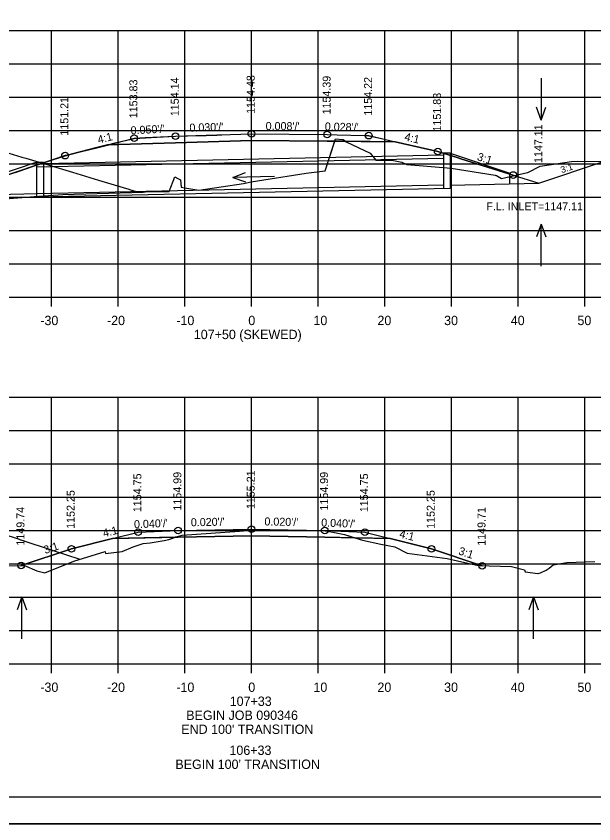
# Model space of a CAD drawing. Extents: x 1368971 to 1374497, y 378717 to 381839.
# Drawn here: x 1369607.6 to 1369694.3, y 378861.8 to 378982.9 of the extents above; entities that cross this region are included whole.
import ezdxf

# ---------------------------------------------------------------- set-up
doc = ezdxf.new("R2010")
doc.units = 0
for name, color, linetype in [('R_Alt Surface', 7, 'Continuous'), ('R_Axis', 7, 'Continuous'), ('R_Axis Annot', 7, 'Continuous'), ('R_Border', 7, 'Continuous'), ('R_Contours', 7, 'Continuous'), ('R_Exist Surface', 7, 'Continuous'), ('R_Fin Surface', 7, 'Continuous'), ('R_Grid', 7, 'Continuous'), ('R_No Plot', 7, 'Continuous'), ('R_Water', 7, 'Continuous'), ('R_Water Annot', 7, 'Continuous'), ('R_Xsect Elev', 7, 'Continuous'), ('R_Xsect Slope', 7, 'Continuous')]:
    doc.layers.add(name, color=color, linetype=linetype)

msp = doc.modelspace()

# ---------------------------------------------------------------- linework, layer by layer
at = {"layer": 'R_Alt Surface'}
for points in [[(1369621.37, 378963.63), (1369631.54, 378963.94), (1369642.93, 378964.29), (1369654.32, 378964.2), (1369664.49, 378964.11)], [(1369622.1, 378904.6), (1369631.93, 378904.8), (1369642.93, 378905.02), (1369653.93, 378904.8), (1369663.76, 378904.6)]]:
    msp.add_lwpolyline(points, dxfattribs=at)
at = {"layer": 'R_Axis'}
for p, q in [((1369502.93, 378940.81), (1369782.93, 378940.81)), ((1369612.93, 378939.41), (1369612.93, 378940.81)), ((1369622.93, 378939.41), (1369622.93, 378940.81)), ((1369632.93, 378939.41), (1369632.93, 378940.81)), ((1369642.93, 378939.41), (1369642.93, 378940.81)), ((1369652.93, 378939.41), (1369652.93, 378940.81)), ((1369662.93, 378939.41), (1369662.93, 378940.81)), ((1369672.93, 378939.41), (1369672.93, 378940.81)), ((1369682.93, 378939.41), (1369682.93, 378940.81)), ((1369692.93, 378939.41), (1369692.93, 378940.81)), ((1369502.93, 378885.81), (1369782.93, 378885.81)), ((1369612.93, 378884.41), (1369612.93, 378885.81)), ((1369622.93, 378884.41), (1369622.93, 378885.81)), ((1369632.93, 378884.41), (1369632.93, 378885.81)), ((1369642.93, 378884.41), (1369642.93, 378885.81)), ((1369652.93, 378884.41), (1369652.93, 378885.81)), ((1369662.93, 378884.41), (1369662.93, 378885.81)), ((1369672.93, 378884.41), (1369672.93, 378885.81)), ((1369682.93, 378884.41), (1369682.93, 378885.81)), ((1369692.93, 378884.41), (1369692.93, 378885.81))]:
    msp.add_line(p, q, dxfattribs=at)
at = {"layer": 'R_Border'}
msp.add_line((1369801.11, 378865.81), (1369484.93, 378865.81), dxfattribs=at)
at = {"layer": 'R_Contours'}
for points in [[(1369655.45, 378964.19), (1369655.56, 378964.52), (1369656.72, 378964.44), (1369657.04, 378964.17)], [(1369657.04, 378964.17), (1369657.13, 378964.1), (1369660.73, 378962.41), (1369661.6, 378961.34), (1369664.27, 378961.28), (1369665.48, 378961.03), (1369666.26, 378960.68), (1369669.28, 378960.43), (1369672.9, 378960.17), (1369679.48, 378959.1), (1369679.59, 378959.05), (1369679.7, 378959.05), (1369680.45, 378958.62), (1369682.22, 378959.02), (1369682.22, 378959.12), (1369681.57, 378959.32), (1369674.37, 378961.55), (1369673.95, 378961.69), (1369670.88, 378962.64), (1369665.6, 378963.86), (1369664.49, 378964.11)], [(1369631.52, 378904.79), (1369631.86, 378904.91), (1369632.54, 378905.11), (1369641.13, 378905.71), (1369642.95, 378905.85), (1369651.96, 378905.81), (1369653.63, 378905.82), (1369654.63, 378905.65), (1369656.91, 378905.21), (1369658.47, 378904.71), (1369653.93, 378904.8), (1369642.93, 378905.02), (1369631.93, 378904.8)], [(1369608.39, 378900.55), (1369608.88, 378900.55), (1369610.73, 378899.78), (1369611.93, 378899.44), (1369616.29, 378901.22), (1369620.99, 378902.65), (1369621.04, 378902.38), (1369623.56, 378902.68), (1369625.22, 378903.35), (1369626.71, 378903.85), (1369627.76, 378903.94), (1369629.87, 378904.33), (1369630.55, 378904.44), (1369631.52, 378904.79), (1369622.1, 378904.6), (1369615.93, 378903.06)], [(1369658.47, 378904.71), (1369659.62, 378904.34), (1369662.35, 378903.75), (1369664.47, 378903.35), (1369666.32, 378902.39), (1369672.32, 378901.6), (1369676.95, 378900.54), (1369677.55, 378900.52), (1369669.93, 378903.06), (1369663.76, 378904.6)]]:
    msp.add_lwpolyline(points, close=True, dxfattribs=at)
msp.add_lwpolyline([(1369602.31, 378955.27), (1369610.34, 378955.89), (1369614.66, 378956.2), (1369626.71, 378956.57), (1369626.8, 378956.58), (1369626.87, 378956.58), (1369627.03, 378956.58), (1369630.6, 378956.64), (1369631.47, 378958.86), (1369631.92, 378958.61), (1369632.28, 378958.41), (1369632.41, 378957.28), (1369632.96, 378957.22), (1369635.06, 378956.85), (1369641.75, 378957.85), (1369642.89, 378958.09), (1369651.16, 378959.38), (1369654.01, 378959.74), (1369655.45, 378964.19), (1369654.32, 378964.2), (1369642.93, 378964.29), (1369631.54, 378963.94), (1369621.37, 378963.63), (1369620.36, 378963.38), (1369619.75, 378963.22), (1369617.27, 378962.6), (1369615.88, 378962.25), (1369615.54, 378962.16), (1369614.98, 378962.02), (1369613.12, 378961.4), (1369610.08, 378960.39), (1369608.05, 378959.71), (1369604.29, 378958.46)], dxfattribs=at)
at = {"layer": 'R_Exist Surface'}
for points in [[(1369602.31, 378955.27), (1369610.34, 378955.89), (1369614.66, 378956.2), (1369626.71, 378956.57), (1369626.8, 378956.58), (1369626.87, 378956.58), (1369627.03, 378956.58), (1369630.6, 378956.64), (1369631.47, 378958.86), (1369631.92, 378958.61), (1369632.28, 378958.41), (1369632.41, 378957.28), (1369632.96, 378957.22), (1369635.06, 378956.85), (1369641.75, 378957.85), (1369642.89, 378958.09), (1369651.16, 378959.38), (1369654.01, 378959.74), (1369655.56, 378964.52), (1369656.72, 378964.44), (1369657.13, 378964.1), (1369660.73, 378962.41), (1369661.6, 378961.34), (1369664.27, 378961.28), (1369665.48, 378961.03), (1369666.26, 378960.68), (1369669.28, 378960.43), (1369672.9, 378960.17), (1369679.48, 378959.1), (1369679.59, 378959.05), (1369679.7, 378959.05), (1369680.45, 378958.62), (1369684.33, 378959.49), (1369684.39, 378959.51), (1369684.71, 378959.64), (1369685.96, 378960.27), (1369686.23, 378960.46), (1369690.95, 378961.14), (1369691.84, 378961.17), (1369699.98, 378961.1)], [(1369600.56, 378900.4), (1369608.88, 378900.55), (1369610.73, 378899.78), (1369611.93, 378899.44), (1369616.29, 378901.22), (1369620.99, 378902.65), (1369621.04, 378902.38), (1369623.56, 378902.68), (1369625.22, 378903.35), (1369626.71, 378903.85), (1369627.76, 378903.94), (1369629.87, 378904.33), (1369630.55, 378904.44), (1369631.86, 378904.91), (1369632.54, 378905.11), (1369641.13, 378905.71), (1369642.95, 378905.85), (1369651.96, 378905.81), (1369653.63, 378905.82), (1369654.63, 378905.65), (1369656.91, 378905.21), (1369659.62, 378904.34), (1369662.35, 378903.75), (1369664.47, 378903.35), (1369666.32, 378902.39), (1369672.32, 378901.6), (1369676.95, 378900.54), (1369681.94, 378900.39), (1369683.9, 378899.92), (1369684, 378899.59), (1369685.9, 378899.38), (1369685.93, 378899.35), (1369686.11, 378899.4), (1369686.3, 378899.45), (1369687.13, 378899.86), (1369687.62, 378900.16), (1369688.18, 378900.64), (1369690.26, 378900.99), (1369694.44, 378901.14)]]:
    msp.add_lwpolyline(points, dxfattribs=at)
at = {"layer": 'R_Fin Surface'}
for p, q in [((1369686.07, 378957.92), (1369695.73, 378961.13)), ((1369682.22, 378959.12), (1369686.07, 378957.92))]:
    msp.add_line(p, q, dxfattribs=at)
for points in [[(1369604.29, 378958.46), (1369608.05, 378959.71), (1369610.08, 378960.39), (1369613.12, 378961.4), (1369614.98, 378962.02), (1369615.54, 378962.16), (1369615.88, 378962.25), (1369617.27, 378962.6), (1369619.75, 378963.22), (1369620.36, 378963.38), (1369621.37, 378963.63), (1369622.5, 378963.92), (1369623.61, 378964.2), (1369625.33, 378964.63), (1369627.02, 378964.72), (1369631.54, 378964.94), (1369636.16, 378965.08), (1369636.42, 378965.09), (1369636.62, 378965.1), (1369636.76, 378965.1), (1369636.88, 378965.11), (1369637.77, 378965.13), (1369638.51, 378965.16), (1369639.75, 378965.19), (1369642.93, 378965.29), (1369654.32, 378965.2), (1369655.82, 378965.15), (1369659.91, 378965.04), (1369660.53, 378965.02), (1369662.25, 378964.63), (1369664.49, 378964.11), (1369665.6, 378963.86), (1369670.88, 378962.64), (1369673.95, 378961.69), (1369674.37, 378961.55), (1369681.57, 378959.32), (1369682.22, 378959.12)], [(1369607.55, 378959.52), (1369608.1, 378959.7), (1369610.1, 378960.37), (1369613.12, 378961.37), (1369614.98, 378961.99), (1369615.54, 378962.13), (1369615.88, 378962.22), (1369617.27, 378962.57), (1369619.75, 378963.2), (1369620.36, 378963.35), (1369621.37, 378963.61), (1369622.5, 378963.9), (1369623.61, 378964.18), (1369625.33, 378964.61), (1369628.77, 378964.78), (1369631.54, 378964.92), (1369635.2, 378965.03), (1369635.54, 378965.04), (1369636.16, 378965.06), (1369636.42, 378965.07), (1369636.62, 378965.08), (1369636.76, 378965.08), (1369636.88, 378965.08), (1369637.77, 378965.11), (1369638.51, 378965.13), (1369639.75, 378965.17), (1369642.93, 378965.27), (1369654.32, 378965.18), (1369655.82, 378965.14), (1369659.91, 378965.03), (1369660.53, 378965.01), (1369662.25, 378964.62), (1369663.06, 378964.43), (1369664.49, 378964.1), (1369664.49, 378964.1), (1369664.49, 378964.1), (1369670.88, 378962.63), (1369673.95, 378961.68), (1369674.76, 378961.43), (1369681.57, 378959.31), (1369682.2, 378959.11)], [(1369605.88, 378962.59), (1369608.52, 378961.79), (1369609.09, 378961.62), (1369616.08, 378959.54), (1369620, 378958.35), (1369620.98, 378958.06), (1369624.54, 378956.99), (1369624.65, 378956.96), (1369626.01, 378956.55)], [(1369564.24, 378898.96), (1369573.02, 378901.92), (1369577.41, 378903.4), (1369577.76, 378903.51), (1369578.22, 378903.67), (1369579.96, 378904.26), (1369581.42, 378904.75), (1369582.43, 378904.77), (1369583.43, 378904.8), (1369598.81, 378905.18), (1369603.47, 378905.29), (1369605.21, 378905.33), (1369605.48, 378905.34), (1369608.08, 378904.49), (1369608.31, 378904.41), (1369608.33, 378904.41), (1369608.48, 378904.36), (1369612.89, 378902.91), (1369617.2, 378901.5)], [(1369608.39, 378900.55), (1369615.93, 378903.06), (1369622.1, 378904.6), (1369625.93, 378905.56), (1369631.93, 378905.8), (1369642.93, 378906.02), (1369653.93, 378905.8), (1369659.93, 378905.56), (1369663.76, 378904.6), (1369669.93, 378903.06), (1369677.55, 378900.52)], [(1369608.39, 378900.55), (1369615.93, 378903.06), (1369622.1, 378904.6), (1369625.93, 378905.56), (1369631.93, 378905.8), (1369642.93, 378906.02), (1369653.93, 378905.8), (1369659.93, 378905.56), (1369663.76, 378904.6), (1369669.93, 378903.06), (1369677.55, 378900.52)]]:
    msp.add_lwpolyline(points, dxfattribs=at)
at = {"layer": 'R_Grid'}
for p, q in [((1369502.93, 378980.81), (1369782.93, 378980.81)), ((1369612.93, 378940.81), (1369612.93, 378980.81)), ((1369622.93, 378940.81), (1369622.93, 378980.81)), ((1369632.93, 378940.81), (1369632.93, 378980.81)), ((1369642.93, 378940.81), (1369642.93, 378980.81)), ((1369652.93, 378940.81), (1369652.93, 378980.81)), ((1369662.93, 378940.81), (1369662.93, 378980.81)), ((1369672.93, 378940.81), (1369672.93, 378980.81)), ((1369682.93, 378940.81), (1369682.93, 378980.81)), ((1369692.93, 378940.81), (1369692.93, 378980.81)), ((1369502.93, 378975.81), (1369782.93, 378975.81)), ((1369502.93, 378970.81), (1369782.93, 378970.81)), ((1369502.93, 378965.81), (1369782.93, 378965.81)), ((1369502.93, 378960.81), (1369782.93, 378960.81)), ((1369502.93, 378955.81), (1369782.93, 378955.81)), ((1369502.93, 378950.81), (1369782.93, 378950.81)), ((1369502.93, 378945.81), (1369782.93, 378945.81)), ((1369502.93, 378940.81), (1369782.93, 378940.81)), ((1369502.93, 378925.81), (1369782.93, 378925.81)), ((1369612.93, 378885.81), (1369612.93, 378925.81)), ((1369622.93, 378885.81), (1369622.93, 378925.81)), ((1369632.93, 378885.81), (1369632.93, 378925.81)), ((1369642.93, 378885.81), (1369642.93, 378925.81)), ((1369652.93, 378885.81), (1369652.93, 378925.81)), ((1369662.93, 378885.81), (1369662.93, 378925.81)), ((1369672.93, 378885.81), (1369672.93, 378925.81)), ((1369682.93, 378885.81), (1369682.93, 378925.81)), ((1369692.93, 378885.81), (1369692.93, 378925.81)), ((1369502.93, 378920.81), (1369782.93, 378920.81)), ((1369502.93, 378915.81), (1369782.93, 378915.81)), ((1369502.93, 378910.81), (1369782.93, 378910.81)), ((1369502.93, 378905.81), (1369782.93, 378905.81)), ((1369502.93, 378900.81), (1369782.93, 378900.81)), ((1369502.93, 378895.81), (1369782.93, 378895.81)), ((1369502.93, 378890.81), (1369782.93, 378890.81)), ((1369502.93, 378885.81), (1369782.93, 378885.81))]:
    msp.add_line(p, q, dxfattribs=at)
at = {"layer": 'R_No Plot'}
msp.add_line((1369472.53, 378861.83), (1369805.86, 378861.83), dxfattribs=at)
for points in [[(1369472.52, 379075.16), (1369805.86, 379075.16), (1369805.86, 378861.82), (1369472.52, 378861.82)], [(1369718.85, 379071.27), (1369718.85, 379061.39), (1369754.58, 379061.39), (1369754.58, 379058.47), (1369777.78, 379058.47), (1369777.78, 379035.25), (1369801.11, 379035.25), (1369801.11, 378865.81), (1369484.93, 378865.81), (1369484.93, 379071.27)]]:
    msp.add_lwpolyline(points, close=True, dxfattribs=at)
for centre in [(1369642.93, 378965.29), (1369654.32, 378965.2), (1369625.33, 378964.63), (1369631.54, 378964.94), (1369660.53, 378965.02), (1369614.98, 378962.02), (1369670.88, 378962.64), (1369682.22, 378959.12), (1369642.93, 378906.02), (1369625.93, 378905.56), (1369631.93, 378905.8), (1369653.93, 378905.8), (1369659.93, 378905.56), (1369615.93, 378903.06), (1369669.93, 378903.06), (1369608.39, 378900.55), (1369677.55, 378900.52)]:
    msp.add_circle(centre, 0.5, dxfattribs=at)
at = {"layer": 'R_Water'}
for p, q in [((1369671.77, 378962.1), (1369611.77, 378960.8)), ((1369672.77, 378962.37), (1369672.77, 378957.12)), ((1369672.77, 378962.37), (1369681.71, 378959.39)), ((1369610.77, 378961.04), (1369601.84, 378958.06)), ((1369671.77, 378961.6), (1369610.77, 378960.28)), ((1369610.77, 378955.79), (1369610.77, 378961.04)), ((1369681.71, 378957.82), (1369681.71, 378959.39)), ((1369671.77, 378957.6), (1369610.77, 378956.28)), ((1369672.77, 378957.62), (1369686.07, 378957.92)), ((1369610.77, 378956.28), (1369596.8, 378955.97)), ((1369672.77, 378957.12), (1369610.77, 378955.78))]:
    msp.add_line(p, q, dxfattribs=at)
for points in [[(1369672.77, 378962.37), (1369671.77, 378962.37), (1369671.77, 378957.1)], [(1369610.77, 378961.04), (1369611.77, 378961.04), (1369611.77, 378955.8)]]:
    msp.add_lwpolyline(points, dxfattribs=at)
at = {"layer": 'R_Water Annot'}
for p, q in [((1369686.4, 378973.63), (1369686.4, 378967.35)), ((1369686.4, 378967.35), (1369685.7, 378969.27)), ((1369686.4, 378967.35), (1369687.1, 378969.27)), ((1369640.13, 378958.74), (1369642.04, 378959.48)), ((1369646.41, 378958.88), (1369640.13, 378958.74)), ((1369640.13, 378958.74), (1369642.07, 378958.08)), ((1369686.4, 378951.75), (1369685.7, 378949.83)), ((1369686.4, 378945.47), (1369686.4, 378951.75)), ((1369686.4, 378951.75), (1369687.1, 378949.83)), ((1369608.5, 378895.87), (1369607.8, 378893.94)), ((1369608.5, 378889.58), (1369608.5, 378895.87)), ((1369608.5, 378895.87), (1369609.2, 378893.94)), ((1369685.26, 378895.87), (1369684.56, 378893.94)), ((1369685.26, 378889.58), (1369685.26, 378895.87)), ((1369685.26, 378895.87), (1369685.96, 378893.94))]:
    msp.add_line(p, q, dxfattribs=at)

# ---------------------------------------------------------------- texts
at = {"layer": 'R_Axis Annot'}
for s, p in [('-30', (1369611.27, 378936.61)), ('-20', (1369621.27, 378936.61)), ('-10', (1369631.67, 378936.61)), ('0', (1369642.47, 378936.61)), ('10', (1369652.24, 378936.61)), ('20', (1369661.84, 378936.61)), ('30', (1369671.84, 378936.61)), ('40', (1369681.84, 378936.61)), ('50', (1369691.84, 378936.61)), ('107+50 (SKEWED)', (1369634.3, 378934.51)), ('-30', (1369611.27, 378881.61)), ('-20', (1369621.27, 378881.61)), ('-10', (1369631.67, 378881.61)), ('0', (1369642.47, 378881.61)), ('10', (1369652.24, 378881.61)), ('20', (1369661.84, 378881.61)), ('30', (1369671.84, 378881.61)), ('40', (1369681.84, 378881.61)), ('50', (1369691.84, 378881.61)), ('107+33', (1369639.68, 378879.51)), ('BEGIN JOB 090346', (1369633.16, 378877.41)), ("END 100' TRANSITION", (1369632.42, 378875.31)), ('106+33', (1369639.64, 378872.16)), ("BEGIN 100' TRANSITION", (1369631.53, 378870.06))]:
    msp.add_text(s, height=1.4, dxfattribs=at).set_placement(p)
at = {"layer": 'R_Water Annot'}
msp.add_text('F.L. INLET=1147.11', height=1.2, dxfattribs=at).set_placement((1369678.18, 378953.82))
at = {"layer": 'R_Xsect Elev'}
for s, p in [('1153.83', (1369625.83, 378967.63)), ('1154.14', (1369632.04, 378967.94)), ('1154.48', (1369643.43, 378968.29)), ('1154.39', (1369654.82, 378968.2)), ('1154.22', (1369661.03, 378968.02)), ('1151.21', (1369615.48, 378965.02)), ('1151.83', (1369671.38, 378965.64)), ('1147.11', (1369686.57, 378960.92)), ('1154.75', (1369626.43, 378908.56)), ('1154.99', (1369632.43, 378908.8)), ('1155.21', (1369643.43, 378909.02)), ('1154.99', (1369654.43, 378908.8)), ('1154.75', (1369660.43, 378908.56)), ('1152.25', (1369616.43, 378906.06)), ('1152.25', (1369670.43, 378906.06)), ('1149.74', (1369608.89, 378903.55)), ('1149.71', (1369678.05, 378903.52))]:
    msp.add_text(s, height=1.2, rotation=90, dxfattribs=at).set_placement(p)
at = {"layer": 'R_Xsect Slope'}
for s, height, rotation, p in [("0.030'/'", 1.2, 1.742, (1369633.66, 378965.61)), ("0.008'/'", 1.2, 359.5288, (1369645.07, 378965.87)), ("0.028'/'", 1.2, 358.4223, (1369653.93, 378965.81)), ("0.050'/'", 1.2, 2.8471, (1369624.85, 378965.21)), ('4:1', 1.2, 14.1751, (1369620.03, 378963.81)), ('4:1', 1.2, 347.0262, (1369665.82, 378964.32)), ('3:1', 1.2, 342.7305, (1369676.7, 378961.36)), ('3:1', 1, 18.4213, (1369689.5, 378959.38)), ("0.040'/'", 1.2, 2.2906, (1369625.35, 378906.14)), ("0.020'/'", 1.2, 1.1458, (1369633.86, 378906.44)), ("0.020'/'", 1.2, 358.8542, (1369644.88, 378906.58)), ("0.040'/'", 1.2, 357.7094, (1369653.39, 378906.42)), ('4:1', 1.2, 14.0362, (1369620.81, 378904.79)), ('4:1', 1.2, 345.9638, (1369665.05, 378904.79)), ('3:1', 1.2, 18.4349, (1369612, 378902.28)), ('3:1', 1.2, 341.5651, (1369673.9, 378902.26))]:
    msp.add_text(s, height=height, rotation=rotation, dxfattribs=at).set_placement(p)

doc.saveas('drawing.dxf')
